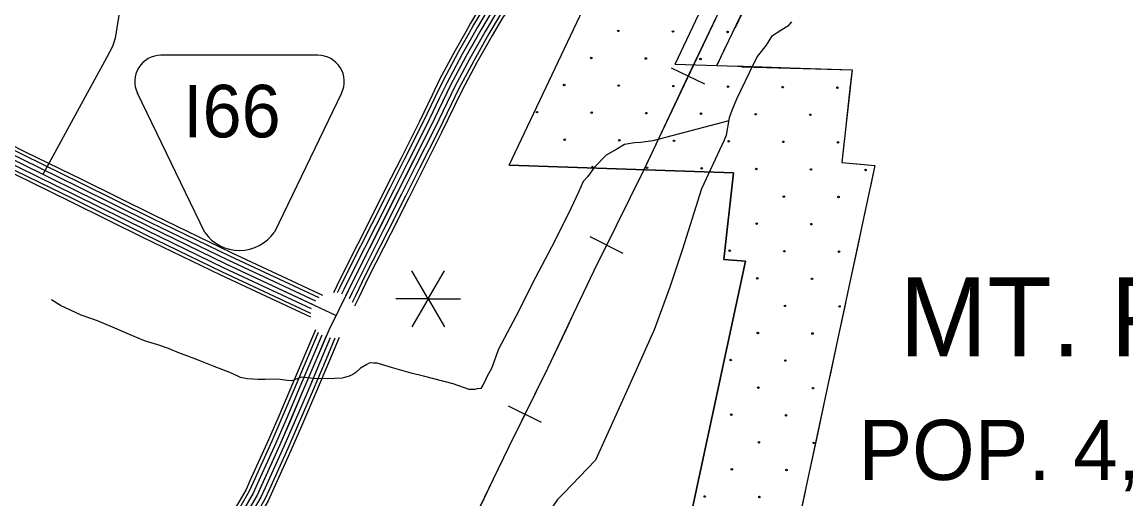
# Model space of a CAD drawing. Extents: x 1551132 to 1791609, y 378168 to 563823.
# Drawn here: x 1607771 to 1615537, y 439390 to 442743 of the extents above; entities that cross this region are included whole.
import ezdxf

# ---------------------------------------------------------------- set-up
doc = ezdxf.new("R2010")
doc.units = 0
for name, color, linetype in [('DESIGN - CONTOURS - Intermediate with optional Text', 7, 'Continuous'), ('DESIGN - EROSION CONTROL - Devices', 7, 'Continuous'), ('DESIGN - ROW - Easement Linework and Patterning', 7, 'Continuous'), ('DESIGN - SCRATCH - User 1', 7, 'Continuous'), ('DESIGN - TRAFFIC CONTROL PERMANENT - Signalization', 7, 'Continuous'), ('DESIGN - TRANSPORTATION - Text', 7, 'Continuous'), ('SURVEY - CONTOURS - Index with Text', 7, 'Continuous'), ('SURVEY - CONTROL with Text', 7, 'Continuous'), ('SURVEY - VEGETATION - Features with Text', 7, 'Continuous')]:
    doc.layers.add(name, color=color, linetype=linetype)

msp = doc.modelspace()

# ---------------------------------------------------------------- linework, layer by layer
at = {"layer": 'DESIGN - CONTOURS - Intermediate with optional Text'}
for p, q in [((1612575.646, 442306.842), (1612340.66, 442418.112)), ((1612000.8, 441115.977), (1611767.889, 441231.514)), ((1611426.863, 439927.379), (1611193.894, 440042.816))]:
    msp.add_line(p, q, dxfattribs=at)
for points in [[(1610934.333, 439209.477), (1611087.471, 439530.352), (1611195.168, 439752.566), (1611471.162, 440309.623), (1611653.658, 440695.841), (1611793.963, 440991.532), (1611952.61, 441311.366), (1612145.231, 441701.576), (1612806.008, 443097.171)], [(1612458.149, 442362.477), (1612740.592, 442959.001)], [(1612175.713, 441765.953), (1612458.149, 442362.477)], [(1611884.345, 441173.746), (1611952.61, 441311.366), (1612145.231, 441701.576), (1612175.713, 441765.953)], [(1611598.41, 440578.913), (1611653.658, 440695.841), (1611793.963, 440991.532), (1611884.345, 441173.746)], [(1611310.374, 439985.097), (1611471.162, 440309.623), (1611598.41, 440578.913)], [(1611021.331, 439391.757), (1611087.471, 439530.352), (1611195.168, 439752.566), (1611310.374, 439985.097)], [(1610725.721, 438802.233), (1610776.686, 438883.252), (1610854.418, 439043.464), (1610934.333, 439209.477), (1611021.331, 439391.757)]]:
    msp.add_lwpolyline(points, dxfattribs=at)
at = {"layer": 'DESIGN - EROSION CONTROL - Devices'}
for points in [[(1611198.386, 441735.593), (1612018.743, 443468.239), (1612462.258, 444413.714)], [(1611198.386, 441735.593), (1612018.743, 443468.239), (1612462.258, 444413.714), (1612507.59, 444392.622)]]:
    msp.add_lwpolyline(points, dxfattribs=at)
for centre in [(1611965.874, 442680.947), (1611965.874, 442680.947), (1612350.427, 442677.214), (1612350.427, 442677.214), (1612734.98, 442673.48), (1612734.98, 442673.48), (1611775.464, 442490.537), (1611775.464, 442490.537), (1612160.017, 442486.804), (1612160.017, 442486.804), (1612544.57, 442483.07), (1612544.57, 442483.07), (1611585.055, 442300.128), (1611585.055, 442300.128), (1611969.608, 442296.394), (1611969.608, 442296.394), (1612354.161, 442292.661), (1612354.161, 442292.661), (1612738.714, 442288.927), (1612738.714, 442288.927), (1613123.267, 442285.194), (1613123.267, 442285.194), (1613507.819, 442281.46), (1613507.819, 442281.46), (1611394.645, 442109.718), (1611394.645, 442109.718), (1611779.198, 442105.985), (1611779.198, 442105.985), (1612163.751, 442102.251), (1612163.751, 442102.251), (1612548.304, 442098.517), (1612548.304, 442098.517), (1612932.857, 442094.784), (1612932.857, 442094.784), (1613317.41, 442091.05), (1613317.41, 442091.05), (1611588.788, 441915.575), (1611588.788, 441915.575), (1611973.341, 441911.841), (1611973.341, 441911.841), (1612357.894, 441908.108), (1612357.894, 441908.108), (1612742.447, 441904.374), (1612742.447, 441904.374), (1613127, 441900.641), (1613127, 441900.641), (1613511.553, 441896.907), (1613511.553, 441896.907), (1612167.484, 441717.698), (1612167.484, 441717.698), (1612552.037, 441713.965), (1612552.037, 441713.965), (1612936.59, 441710.231), (1612936.59, 441710.231), (1613321.143, 441706.497), (1613321.143, 441706.497), (1613705.696, 441702.764), (1613705.696, 441702.764), (1613130.734, 441516.088), (1613130.734, 441516.088), (1613515.287, 441512.354), (1613515.287, 441512.354), (1612940.324, 441325.678), (1612940.324, 441325.678), (1613324.877, 441321.945), (1613324.877, 441321.945), (1612749.914, 441135.268), (1612749.914, 441135.268), (1613134.467, 441131.535), (1613134.467, 441131.535), (1613519.02, 441127.801), (1613519.02, 441127.801), (1612944.057, 440941.125), (1612944.057, 440941.125), (1613328.61, 440937.392), (1613328.61, 440937.392), (1613138.201, 440746.982), (1613138.201, 440746.982), (1613522.754, 440743.248), (1613522.754, 440743.248), (1612947.791, 440556.572), (1612947.791, 440556.572), (1613332.344, 440552.839), (1613332.344, 440552.839), (1612757.381, 440366.162), (1612757.381, 440366.162), (1613141.934, 440362.429), (1613141.934, 440362.429), (1612951.524, 440172.019), (1612951.524, 440172.019), (1613336.077, 440168.286), (1613336.077, 440168.286), (1612761.115, 439981.609), (1612761.115, 439981.609), (1613145.668, 439977.876), (1613145.668, 439977.876), (1612955.258, 439787.466), (1612955.258, 439787.466), (1613339.811, 439783.733), (1613339.811, 439783.733), (1612764.848, 439597.057), (1612764.848, 439597.057), (1613149.401, 439593.323), (1613149.401, 439593.323), (1612574.439, 439406.647), (1612574.439, 439406.647), (1612958.992, 439402.913), (1612958.992, 439402.913)]:
    msp.add_circle(centre, 5.28, dxfattribs=at)
for centre, start, end in [((1611398.379, 441725.165), 45.1282492, 131.1121971), ((1611782.932, 441721.432), 286.1511563, 250.08929)]:
    msp.add_arc(centre, 5.28, start, end, dxfattribs=at)
at = {"layer": 'DESIGN - ROW - Easement Linework and Patterning'}
for p, q in [((1609853.176, 442509.392), (1608748.803, 442509.369)), ((1609056.925, 441263.583), (1608582.448, 442244.086)), ((1610019.509, 442244.117), (1609546.474, 441266.501))]:
    msp.add_line(p, q, dxfattribs=at)
for centre, radius, start, end in [((1608748.801, 442324.566), 184.803, 90.0012194, 205.8236083), ((1609853.166, 442324.59), 184.803, 334.1799278, 90.0012194), ((1609300.688, 441435.141), 298.08, 215.1370611, 325.5451333)]:
    msp.add_arc(centre, radius, start, end, dxfattribs=at)
at = {"layer": 'DESIGN - SCRATCH - User 1'}
for points in [[(1613299.263, 443794.857), (1612959.562, 443067.662), (1612658.411, 442439.879)], [(1611198.386, 441735.593), (1612018.743, 443468.239)], [(1612834.282, 442427.829), (1613610.463, 442406.837), (1613538.081, 441754.295), (1613771.451, 441733.986), (1613187.288, 439009.098)], [(1612338.658, 438628.413), (1612860.03, 441060.452), (1612708, 441073.677), (1612775.683, 441683.826), (1611198.386, 441735.593)]]:
    msp.add_lwpolyline(points, dxfattribs=at)
at = {"layer": 'DESIGN - TRAFFIC CONTROL PERMANENT - Signalization'}
for q in [(1610514.419, 440994.499), (1610742.519, 440994.504), (1610400.374, 440796.979), (1610514.429, 440599.466), (1610856.565, 440796.991), (1610742.529, 440599.471)]:
    msp.add_line((1610628.474, 440796.985), q, dxfattribs=at)
at = {"layer": 'DESIGN - TRANSPORTATION - Text'}
for points in [[(1613184.149, 442745.079), (1613169.966, 442727.195), (1613159.841, 442715.27), (1613117.542, 442687.653), (1613045.052, 442642.31), (1613006.336, 442579.975), (1612942.446, 442501.848), (1612889.197, 442391.753), (1612825.307, 442260.358), (1612796.907, 442199.981), (1612764.966, 442121.854), (1612747.217, 442068.578), (1612725.917, 441947.833), (1612710.626, 441911.765)], [(1612743.467, 442047.319), (1612209.188, 441908.39), (1612125.123, 441896.698), (1612081.099, 441894.873), (1612067.083, 441890.923), (1612009.042, 441883.139), (1611954.919, 441849.288), (1611880.77, 441807.504), (1611798.489, 441721.668), (1611750.273, 441653.725), (1611718.166, 441621.791), (1611685.933, 441545.772), (1611615.468, 441395.76), (1611496.737, 441159.77), (1611384.073, 440945.806), (1611245.218, 440671.824), (1611122.504, 440441.868), (1611074.088, 440305.789), (1611041.906, 440247.804), (1611027.806, 440215.803), (1611013.731, 440189.803), (1610999.648, 440165.819), (1610973.641, 440163.919), (1610955.616, 440157.977), (1610917.609, 440160.135), (1610803.678, 440198.669), (1610595.758, 440253.612), (1610509.785, 440273.996), (1610377.855, 440312.597), (1610269.899, 440343.09), (1610243.899, 440345.198), (1610219.892, 440347.298), (1610213.883, 440345.323), (1610195.851, 440335.373), (1610151.76, 440309.497), (1610119.652, 440277.563), (1610099.603, 440263.621), (1610071.562, 440251.712), (1610023.505, 440239.878), (1609919.457, 440234.286), (1609819.426, 440236.695), (1609737.42, 440245.037), (1609669.321, 440219.261), (1609635.314, 440223.403), (1609571.315, 440231.678), (1609481.276, 440230.036), (1609431.26, 440230.236), (1609395.253, 440232.386), (1609355.245, 440234.553), (1609307.255, 440242.761), (1609245.323, 440275.07), (1609123.409, 440319.647), (1609017.495, 440362.156), (1608937.555, 440394.54), (1608879.598, 440414.816), (1608801.658, 440447.191), (1608725.71, 440473.55), (1608633.762, 440501.968), (1608543.831, 440538.402), (1608407.951, 440597.062), (1608302.045, 440641.579), (1608188.123, 440682.114), (1608042.268, 440750.832), (1607978.353, 440789.166)], [(1612710.626, 441911.765), (1612552.254, 441570.065), (1612418.474, 441146.295), (1612329.284, 440878.655), (1612217.803, 440577.555), (1612028.274, 440153.794), (1611805.304, 439663.114), (1611582.326, 439428.933), (1611537.735, 439384.324), (1611370.506, 439138.984), (1611247.867, 438915.953), (1611114.086, 438726.373), (1610951.632, 438605.394)]]:
    msp.add_lwpolyline(points, dxfattribs=at)
at = {"layer": 'SURVEY - CONTOURS - Index with Text'}
msp.add_lwpolyline([(1608871.051, 445517.624), (1608851.36, 445390.279), (1608794.311, 445014.261), (1608724.629, 444592.308), (1608617.906, 443944.391), (1608551.349, 443454.253), (1608483.017, 442982.182), (1608426.277, 442630.207), (1608407.477, 442572.338), (1608364.312, 442490.761), (1608187.632, 442164.478), (1607917.646, 441672.09)], dxfattribs=at)
at = {"layer": 'SURVEY - CONTROL with Text'}
for points in [[(1611180.246, 443098.779), (1611118.689, 443019.143), (1611010.683, 442876.598), (1610927.06, 442734.936), (1610893.352, 442675.409)], [(1611199.804, 443083.662), (1611138.313, 443004.118), (1611031.241, 442862.806), (1610948.459, 442722.561), (1610914.86, 442663.226)], [(1611224.328, 443064.695), (1611162.93, 442985.276), (1611057.032, 442845.514), (1610975.292, 442707.043), (1610941.834, 442647.95)], [(1611248.853, 443045.736), (1611187.546, 442966.434), (1611082.815, 442828.213), (1611002.133, 442691.526), (1610968.809, 442632.675)], [(1611273.377, 443026.777), (1611212.162, 442947.592), (1611108.597, 442810.913), (1611028.974, 442676.009), (1610995.783, 442617.399)], [(1611297.901, 443007.81), (1611236.778, 442928.749), (1611134.388, 442793.621), (1611055.807, 442660.492), (1611022.758, 442602.124)], [(1611318.243, 442992.084), (1611257.202, 442913.116), (1611155.78, 442779.27), (1611078.073, 442647.617), (1611045.132, 442589.449)], [(1609861.942, 440803.576), (1609233.632, 441097.292), (1608690.728, 441360.007), (1608185.124, 441610.188), (1607784.708, 441806.201), (1607211.738, 442095.792), (1606767.066, 442314.997), (1606390.566, 442498.46), (1606132.714, 442629.747), (1606010.342, 442688.857), (1605912.811, 442732.633), (1605803.097, 442766.625), (1605645.517, 442800.534), (1605459.022, 442831.893)], [(1609887.166, 440820.168), (1609244.673, 441120.518), (1608702.036, 441383.107), (1608196.482, 441633.264), (1607796.158, 441829.227), (1607223.221, 442118.801), (1606778.382, 442338.09), (1606402.033, 442521.477), (1606144.147, 442652.781), (1606021.2, 442712.174), (1605921.911, 442756.733), (1605809.622, 442791.526), (1605650.359, 442825.802), (1605485.121, 442853.586)], [(1611082.815, 442828.213), (1611002.133, 442691.526), (1610894.411, 442501.271), (1610786.455, 442298.991), (1610644.733, 442005.2), (1610413.788, 441546.838), (1610130.869, 440987.298), (1609930.932, 440580.437), (1609754.861, 440165.085), (1609585.173, 439769.657), (1609424.293, 439416.123), (1609362.203, 439309.137)], [(1609979.864, 440680.007), (1609206.999, 441041.299), (1608663.479, 441304.314), (1608157.749, 441554.562), (1607757.092, 441750.683), (1607184.047, 442040.315), (1606739.783, 442259.321), (1606362.917, 442442.959), (1606105.165, 442574.195), (1605984.159, 442632.647), (1605890.861, 442674.523), (1605787.372, 442706.59), (1605633.851, 442739.624), (1605364.449, 442784.925)], [(1609808.718, 440725.791), (1609193.683, 441013.306), (1608649.854, 441276.471), (1608144.058, 441526.744), (1607743.284, 441722.924), (1607170.206, 442012.581), (1606726.141, 442231.487), (1606349.092, 442415.208), (1606091.39, 442546.42), (1605971.068, 442604.546), (1605879.887, 442645.472), (1605779.506, 442676.573), (1605628.017, 442709.165), (1605432.664, 442742.016)], [(1609820.351, 440754.575), (1609206.999, 441041.299), (1608663.479, 441304.314), (1608157.749, 441554.562), (1607757.092, 441750.683), (1607184.047, 442040.315), (1606739.783, 442259.321), (1606362.917, 442442.959), (1606105.165, 442574.195), (1605984.159, 442632.647), (1605890.861, 442674.523), (1605787.372, 442706.59), (1605633.851, 442739.624), (1605441.289, 442772.008)], [(1609837.368, 440780.834), (1609220.316, 441069.291), (1608677.103, 441332.156), (1608171.44, 441582.379), (1607770.9, 441778.442), (1607197.889, 442068.049), (1606753.424, 442287.155), (1606376.741, 442470.709), (1606118.939, 442601.971), (1605997.25, 442660.748), (1605901.836, 442703.574), (1605795.239, 442736.608), (1605639.684, 442770.084), (1605448.255, 442802.276)], [(1609802.593, 440667.148), (1609169.75, 440962.988), (1608625.363, 441226.42), (1608119.458, 441476.751), (1607718.468, 441673.039), (1607145.323, 441962.722), (1606701.617, 442181.452), (1606324.251, 442365.332), (1606066.632, 442496.502), (1605947.543, 442554.028), (1605860.162, 442593.246), (1605765.373, 442622.621), (1605617.534, 442654.43), (1605419.489, 442687.731)], [(1609803.56, 440693.982), (1609180.366, 440985.306), (1608636.229, 441248.621), (1608130.375, 441498.935), (1607729.476, 441695.165), (1607156.356, 441984.839), (1606712.5, 442203.644), (1606335.267, 442387.457), (1606077.615, 442518.644), (1605957.976, 442576.437), (1605868.912, 442616.413), (1605771.647, 442646.555), (1605622.184, 442678.714), (1605432.222, 442710.657)], [(1610893.361, 442675.418), (1610818.421, 442543.056), (1610709.123, 442338.267), (1610656.349, 442228.856)], [(1610914.868, 442663.242), (1610840.078, 442531.147), (1610731.164, 442327.067), (1610678.607, 442218.122)], [(1610941.843, 442647.967), (1610867.244, 442516.213), (1610758.805, 442313.033), (1610706.523, 442204.647)], [(1610968.817, 442632.692), (1610894.411, 442501.271), (1610786.455, 442298.991), (1610734.447, 442191.18)], [(1610995.792, 442617.416), (1610921.577, 442486.329), (1610814.104, 442284.949), (1610762.372, 442177.713)], [(1611022.766, 442602.141), (1610948.743, 442471.396), (1610841.745, 442270.915), (1610790.288, 442164.238)], [(1611045.149, 442589.474), (1610971.275, 442459.004), (1610864.678, 442259.265), (1610813.446, 442153.062)], [(1610656.358, 442228.872), (1610566.96, 442043.551), (1610435.229, 441782.102)], [(1610678.615, 442218.139), (1610589.126, 442032.617), (1610457.304, 441770.985)], [(1610706.531, 442204.664), (1610616.925, 442018.909), (1610484.986, 441757.035)], [(1610734.456, 442191.197), (1610644.733, 442005.2), (1610512.669, 441743.085)], [(1610762.38, 442177.73), (1610672.54, 441991.491), (1610540.352, 441729.134)], [(1610790.296, 442164.254), (1610700.34, 441977.783), (1610568.034, 441715.184)], [(1610813.454, 442153.079), (1610723.406, 441966.407), (1610591, 441703.617)], [(1610435.238, 441782.127), (1610336.373, 441585.914), (1610209.951, 441335.882)], [(1610457.312, 441771.002), (1610358.439, 441574.78), (1610232.009, 441324.724)], [(1610484.995, 441757.052), (1610386.114, 441560.805), (1610259.666, 441310.74)], [(1610512.677, 441743.101), (1610413.788, 441546.838), (1610287.332, 441296.748)], [(1610540.36, 441729.151), (1610441.462, 441532.871), (1610314.998, 441282.756)], [(1610568.043, 441715.201), (1610469.137, 441518.895), (1610342.656, 441268.772)], [(1610591.009, 441703.625), (1610492.094, 441507.312), (1610365.605, 441257.164)], [(1610209.959, 441335.899), (1610053.263, 441025.991), (1609985.464, 440888.02)], [(1610232.017, 441324.74), (1610075.379, 441014.957), (1610007.647, 440877.112)], [(1610259.675, 441310.757), (1610103.128, 441001.132), (1610035.463, 440863.445)], [(1610287.341, 441296.765), (1610130.869, 440987.298), (1610063.287, 440849.769)], [(1610315.007, 441282.772), (1610158.61, 440973.464), (1610091.112, 440836.094)], [(1610342.664, 441268.789), (1610186.36, 440959.639), (1610118.928, 440822.427)], [(1610365.614, 441257.18), (1610209.367, 440948.164), (1610142.01, 440811.085)], [(1609985.473, 440888.037), (1609961.631, 440839.519)], [(1610007.655, 440877.128), (1609988.614, 440838.377)], [(1610035.471, 440863.461), (1610018.688, 440829.302)], [(1610063.296, 440849.786), (1610046.679, 440815.985)], [(1610091.12, 440836.111), (1610072.254, 440797.718)], [(1610118.936, 440822.444), (1610093.812, 440771.317)], [(1610142.019, 440811.093), (1610109.378, 440744.683)], [(1609835.926, 440578.487), (1609773.077, 440430.242)], [(1609854.6, 440559.228), (1609795.835, 440420.6)], [(1609880.991, 440542.053), (1609824.376, 440408.499)], [(1609909.141, 440529.028), (1609852.917, 440396.399)], [(1609939.532, 440521.302), (1609881.458, 440384.299)], [(1609972.639, 440519.961), (1609909.999, 440372.198)], [(1610002.597, 440524.761), (1609933.673, 440362.165)], [(1609773.086, 440430.267), (1609675.096, 440199.11), (1609577.073, 439970.688)], [(1609795.843, 440420.616), (1609697.837, 440189.41), (1609599.789, 439960.937)], [(1609824.384, 440408.516), (1609726.345, 440177.252), (1609628.272, 439948.712)], [(1609852.925, 440396.416), (1609754.861, 440165.085), (1609656.763, 439936.487)], [(1609881.466, 440384.315), (1609783.377, 440152.918), (1609685.254, 439924.262)], [(1609910.007, 440372.215), (1609811.884, 440140.759), (1609713.737, 439912.036)], [(1609933.682, 440362.182), (1609835.542, 440130.667), (1609737.369, 439901.894)], [(1609577.082, 439970.704), (1609505.858, 439804.717), (1609374.353, 439515.726)], [(1609599.798, 439960.954), (1609528.466, 439794.725), (1609396.844, 439505.492)], [(1609628.28, 439948.729), (1609556.815, 439782.191), (1609425.06, 439492.65)], [(1609656.771, 439936.504), (1609585.173, 439769.657), (1609453.276, 439479.808)], [(1609685.262, 439924.278), (1609613.531, 439757.124), (1609481.492, 439466.966)], [(1609713.745, 439912.053), (1609641.88, 439744.59), (1609509.708, 439454.124)], [(1609737.378, 439901.911), (1609665.404, 439734.19), (1609533.116, 439443.474)], [(1609374.361, 439515.751), (1609347.145, 439455.949), (1609288.288, 439354.538), (1609153.266, 439146.483), (1609122.708, 439099.048)], [(1609396.852, 439505.509), (1609369.136, 439444.599), (1609309.354, 439341.596), (1609174.024, 439133.057), (1609143.483, 439085.664)], [(1609425.068, 439492.667), (1609396.71, 439430.357), (1609335.778, 439325.362), (1609200.048, 439116.223), (1609169.541, 439068.872)], [(1609453.284, 439479.825), (1609424.293, 439416.123), (1609362.203, 439309.137), (1609226.081, 439099.39), (1609195.598, 439052.08)], [(1609481.5, 439466.983), (1609451.876, 439401.889), (1609388.627, 439292.912), (1609252.114, 439082.556), (1609221.656, 439035.288)], [(1609509.716, 439454.141), (1609479.45, 439387.647), (1609415.052, 439276.678), (1609278.138, 439065.722), (1609247.714, 439018.496)], [(1609533.116, 439443.491), (1609502.333, 439375.839), (1609436.968, 439263.219), (1609299.737, 439051.755), (1609269.33, 439004.571)]]:
    msp.add_lwpolyline(points, dxfattribs=at)
at = {"layer": 'SURVEY - VEGETATION - Features with Text'}
for points in [[(1611198.386, 441735.593), (1612018.743, 443468.239), (1612462.258, 444413.714)], [(1612365.359, 442447.721), (1612697.152, 443148.481), (1613141.242, 444095.173)], [(1612791.033, 442704.236), (1612904.005, 442942.842)], [(1612664.094, 442445.438), (1612723.243, 442570.358)], [(1612365.359, 442447.721), (1613610.463, 442406.837), (1613538.081, 441754.295), (1613771.451, 441733.986), (1613187.288, 439009.098)], [(1612779.116, 442434.137), (1613042.968, 442425.471)], [(1613042.96, 442425.471), (1613306.812, 442416.804)], [(1613456.725, 442411.887), (1613610.463, 442406.837), (1613598.314, 442297.326)], [(1613598.314, 442297.334), (1613569.214, 442034.936)], [(1613552.673, 441885.849), (1613538.081, 441754.295), (1613669.228, 441742.887)], [(1611198.386, 441735.593), (1612775.683, 441683.826), (1612708, 441073.677), (1612860.03, 441060.452), (1612338.658, 438628.413)], [(1613669.22, 441742.887), (1613771.451, 441733.986), (1613737.618, 441576.191)], [(1613706.177, 441429.52), (1613650.837, 441171.38)], [(1613650.837, 441171.388), (1613595.496, 440913.248)], [(1613564.055, 440766.578), (1613508.715, 440508.429)], [(1613508.715, 440508.438), (1613453.374, 440250.297)], [(1613421.933, 440103.627), (1613366.593, 439845.487)], [(1613366.593, 439845.495), (1613311.252, 439587.355)], [(1613279.811, 439440.684), (1613224.471, 439182.544)]]:
    msp.add_lwpolyline(points, dxfattribs=at)

# ---------------------------------------------------------------- texts
at = {"layer": 'DESIGN - ROW - Easement Linework and Patterning'}
msp.add_text('I66', height=369.6052, rotation=0.0012194, dxfattribs=at).set_placement((1608903.875, 441931.997))
at = {"layer": 'SURVEY - VEGETATION - Features with Text'}
for s, height, p in [('MT. PLEASANT', 554.98698, (1613943.863, 440392.943)), ('POP. 4,278 (EST.)', 422.99008, (1613656.344, 439522.695))]:
    msp.add_text(s, height=height, rotation=0.0000333, dxfattribs=at).set_placement(p)

doc.saveas('drawing.dxf')
